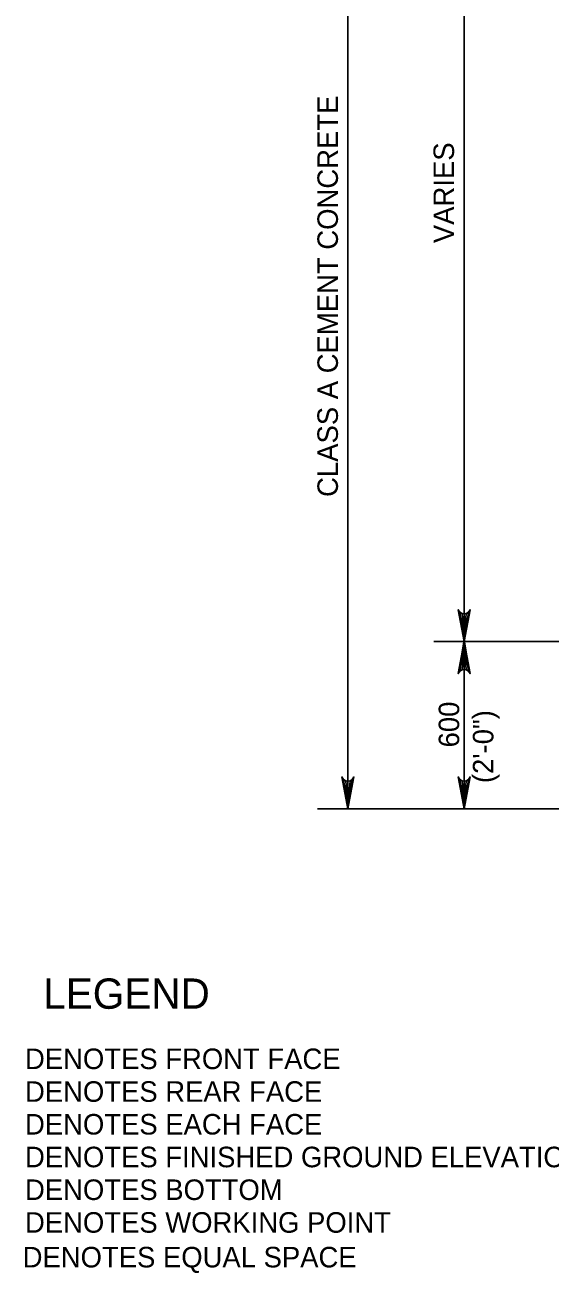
# Model space of a CAD drawing. Extents: x 634540 to 640306, y 296059 to 300275.
# Drawn here: x 638957.2 to 639034, y 296944.4 to 297126.7 of the extents above; entities that cross this region are included whole.
import ezdxf

# ---------------------------------------------------------------- set-up
doc = ezdxf.new("R2010")
doc.units = 0
doc.layers.add('3', color=7, linetype='Continuous')
doc.layers.add('4', color=7, linetype='Continuous')

msp = doc.modelspace()

# ---------------------------------------------------------------- linework, layer by layer
at = {"layer": '3'}
for p, q in [((639004.42, 297012.19), (639004.42, 297173.91)), ((639021.42, 297173.91), (639021.42, 297105.27)), ((639021.42, 297036.62), (639021.42, 297105.27)), ((639072.62, 297036.62), (639016.99, 297036.62)), ((639021.42, 297012.19), (639021.42, 297036.62)), ((639030.49, 297012.19), (638999.99, 297012.19))]:
    msp.add_line(p, q, dxfattribs=at)
for points in [[(639021.42, 297036.62), (639020.55, 297041.28), (639020.8, 297040.92), (639021.11, 297040.74), (639021.42, 297040.68), (639021.73, 297040.74), (639022.05, 297040.92), (639022.29, 297041.28), (639021.42, 297036.62), (639022.05, 297040.92), (639021.73, 297040.74), (639021.42, 297036.62), (639021.42, 297040.68), (639021.11, 297040.74), (639021.42, 297036.62), (639020.8, 297040.92)], [(639021.42, 297036.62), (639022.29, 297031.96), (639022.05, 297032.32), (639021.73, 297032.5), (639021.42, 297032.56), (639021.11, 297032.5), (639020.8, 297032.32), (639020.55, 297031.96), (639021.42, 297036.62), (639020.8, 297032.32), (639021.11, 297032.5), (639021.42, 297036.62), (639021.42, 297032.56), (639021.73, 297032.5), (639021.42, 297036.62), (639022.05, 297032.32)], [(639004.42, 297012.19), (639003.54, 297016.85), (639003.79, 297016.49), (639004.1, 297016.3), (639004.42, 297016.25), (639004.73, 297016.3), (639005.04, 297016.49), (639005.29, 297016.85), (639004.42, 297012.19), (639005.04, 297016.49), (639004.73, 297016.3), (639004.42, 297012.19), (639004.42, 297016.25), (639004.1, 297016.3), (639004.42, 297012.19), (639003.79, 297016.49)], [(639021.42, 297012.19), (639020.55, 297016.85), (639020.8, 297016.49), (639021.11, 297016.3), (639021.42, 297016.25), (639021.73, 297016.3), (639022.05, 297016.49), (639022.29, 297016.85), (639021.42, 297012.19), (639022.05, 297016.49), (639021.73, 297016.3), (639021.42, 297012.19), (639021.42, 297016.25), (639021.11, 297016.3), (639021.42, 297012.19), (639020.8, 297016.49)]]:
    msp.add_lwpolyline(points, dxfattribs=at)
for points in [[(639021.91, 297039.57), (639020.93, 297039.57), (639021.42, 297036.62)], [(639021.91, 297033.93), (639020.93, 297033.93), (639021.42, 297036.88)], [(639003.93, 297015.14), (639004.91, 297015.14), (639004.42, 297012.19)], [(639021.91, 297015.14), (639020.93, 297015.14), (639021.42, 297012.19)]]:
    msp.add_lwpolyline(points, close=True, dxfattribs=at)
at = {"layer": '4'}
msp.add_line((639014.28, 297012.19), (639073.24, 297012.19), dxfattribs=at)

# ---------------------------------------------------------------- texts
at = {"layer": '3'}
for s, height, p in [('CLASS A CEMENT CONCRETE', 3.0001, (639002.96, 297057.75)), ('VARIES', 3, (639019.94, 297094.82)), ('600', 3, (639020.69, 297021.16)), ('(2\'-0")', 3, (639025.69, 297015.95))]:
    msp.add_text(s, height=height, rotation=90, dxfattribs=at).set_placement(p)
for s, height, p in [('LEGEND', 4.429, (638959.87, 296982.99)), ('DENOTES FRONT FACE', 3.0001, (638957.21, 296974.18)), ('DENOTES REAR FACE', 3.0001, (638957.21, 296969.4)), ('DENOTES EACH FACE', 3.0001, (638957.21, 296964.62)), ('DENOTES FINISHED GROUND ELEVATION', 3.0001, (638957.21, 296959.84)), ('DENOTES BOTTOM', 3.0001, (638957.21, 296955.06)), ('DENOTES WORKING POINT', 3.0001, (638957.21, 296950.28)), ('DENOTES EQUAL SPACE', 3.0001, (638956.87, 296945.21))]:
    msp.add_text(s, height=height, dxfattribs=at).set_placement(p)

doc.saveas('drawing.dxf')
